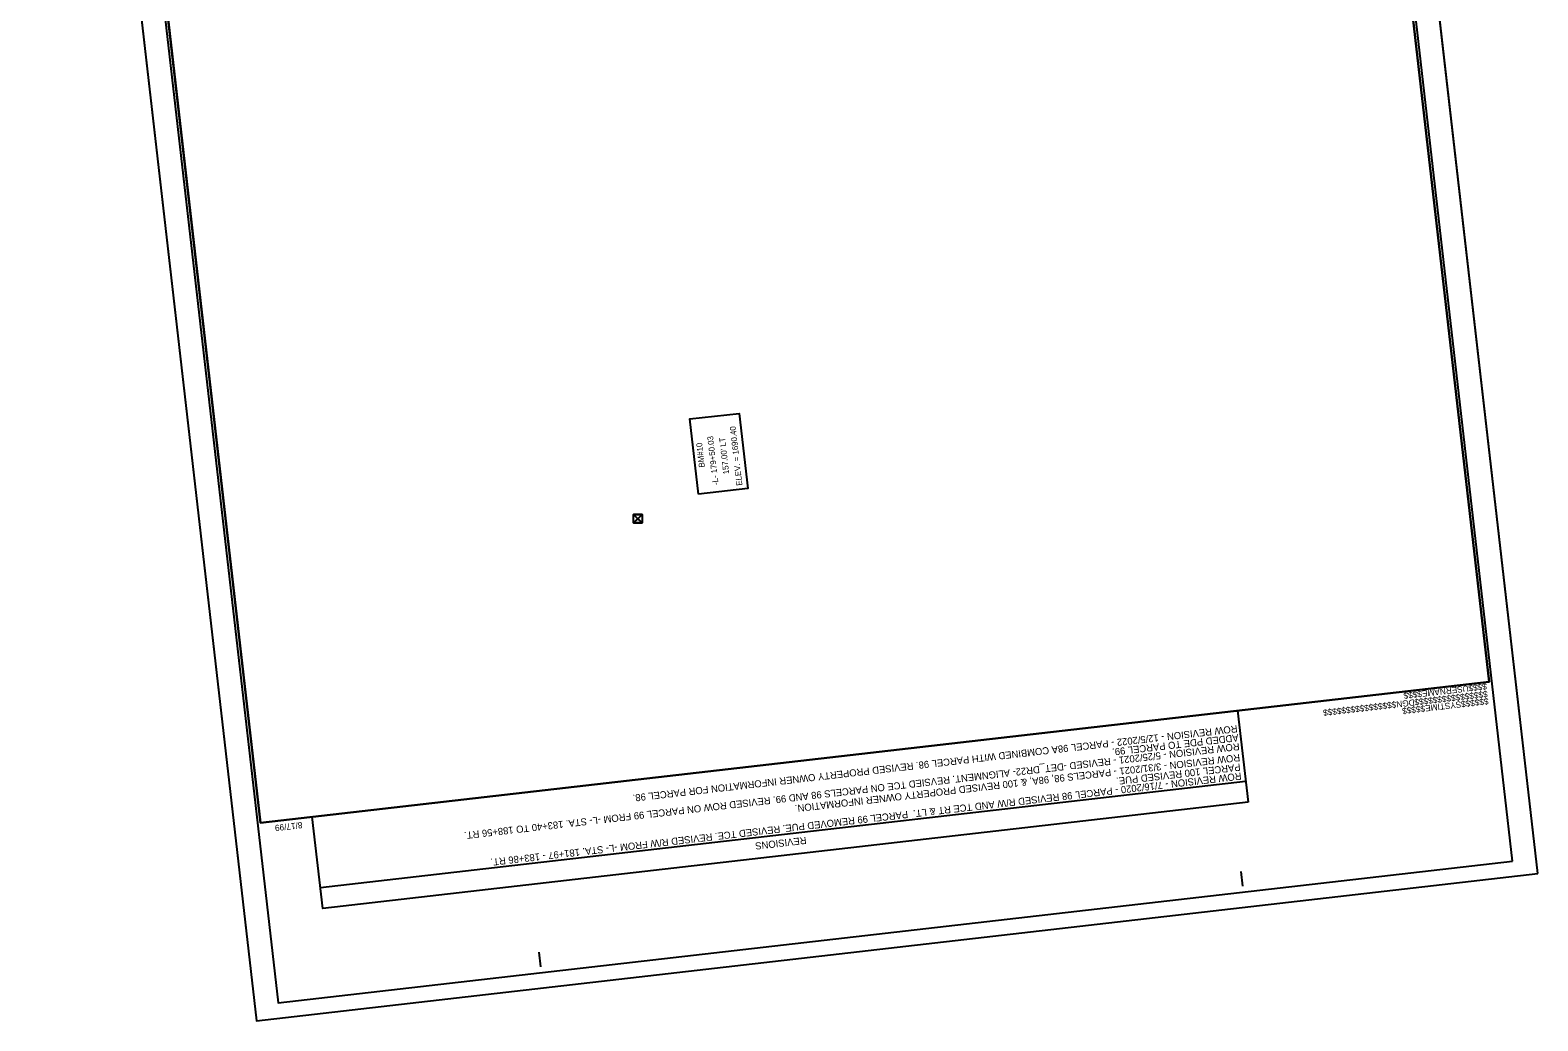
# Model space of a CAD drawing. Extents: x 474105 to 475385, y 502977 to 504774.
# Drawn here: x 474105 to 475385, y 502977 to 503817 of the extents above; entities that cross this region are included whole.
import ezdxf

# ---------------------------------------------------------------- set-up
doc = ezdxf.new("R2010")
doc.units = 0
for name, color, linetype in [('Default', 7, 'Continuous'), ('Prop Dimension Text', 7, 'Continuous'), ('Prop Grid Mask', 7, 'Continuous'), ('Sheet Block Revision CELL', 7, 'Continuous'), ('Sheet Cutting Line CELL', 7, 'Continuous'), ('Sheet Layout Plan Border', 7, 'Continuous'), ('Sheet Plan CELL', 7, 'Continuous'), ('Sheet Plan Layout CELL', 7, 'Continuous'), ('Sheet Plot Border Inside CELL', 7, 'Continuous'), ('Sheet Plot Border Outside CELL', 7, 'Continuous')]:
    doc.layers.add(name, color=color, linetype=linetype)

msp = doc.modelspace()

# ---------------------------------------------------------------- linework, layer by layer
at = {"layer": 'Default'}
msp.add_line((474621.3, 503402.8), (474621.3, 503402.8), dxfattribs=at)
msp.add_lwpolyline([(474617.7, 503406.4), (474624.9, 503406.4), (474624.9, 503399.2), (474617.7, 503399.2)], close=True, dxfattribs=at)
for points in [[(474624.9, 503406.4), (474617.7, 503399.2), (474621.3, 503402.8), (474624.9, 503399.2), (474617.7, 503406.4)], [(474621.3, 503402.8), (474624.9, 503406.4), (474617.7, 503406.4), (474621.3, 503402.8)], [(474621.3, 503402.8), (474617.7, 503399.2), (474624.9, 503399.2), (474621.3, 503402.8)]]:
    msp.add_lwpolyline(points, dxfattribs=at)
at = {"layer": 'Prop Grid Mask'}
msp.add_lwpolyline([(474672.7, 503423.5), (474665.4, 503487.4), (474707.3, 503492.2), (474714.6, 503428.3)], close=True, dxfattribs=at)
at = {"layer": 'Sheet Block Revision CELL'}
msp.add_line((475137.3, 503179.9), (474351.9, 503089.6), dxfattribs=at)
msp.add_lwpolyline([(475139.4, 503162.4), (474353.9, 503072.1), (474344.9, 503149.8), (475130.4, 503240)], close=True, dxfattribs=at)
at = {"layer": 'Sheet Cutting Line CELL'}
for p, q in [((475385.4, 503101.7), (475193.2, 504774.2)), ((474105.4, 504649.2), (474297.5, 502976.7)), ((474297.5, 502976.7), (475385.4, 503101.7))]:
    msp.add_line(p, q, dxfattribs=at)
at = {"layer": 'Sheet Layout Plan Border'}
msp.add_lwpolyline([(475344, 503264.5), (475192.3, 504585.3), (475112.8, 504576.2), (474903.6, 504485.2), (474306.1, 504619.7), (474302.1, 504654.7), (474324.9, 504456), (474152.5, 504436.2), (474168.8, 504438), (474279.8, 503999.6), (474242, 503987.6), (474254.8, 503913.6), (474216.7, 503877.5), (474300.9, 503144.7)], close=True, dxfattribs=at)
at = {"layer": 'Sheet Plan CELL'}
for p, q in [((475344, 503264.5), (475344, 503264.5)), ((474300.9, 503144.7), (474300.9, 503144.7)), ((475135, 503091.1), (475133.6, 503103.5)), ((474538.9, 503022.6), (474537.5, 503035))]:
    msp.add_line(p, q, dxfattribs=at)
for points in [[(474129.7, 504634.9), (474300.9, 503144.7), (475344, 503264.5), (475172.8, 504754.7)], [(475344, 503264.5), (474300.9, 503144.7), (474152.5, 504436.2), (474301.6, 504453.3), (474278.8, 504652), (475172.8, 504754.7)]]:
    msp.add_lwpolyline(points, close=True, dxfattribs=at)
at = {"layer": 'Sheet Plan Layout CELL'}
msp.add_lwpolyline([(474300.9, 503144.7), (475344, 503264.5), (475172.8, 504754.7), (474339.8, 504659), (474367.1, 504421.3), (474157, 504397.2)], close=True, dxfattribs=at)
at = {"layer": 'Sheet Plot Border Inside CELL'}
msp.add_lwpolyline([(475364, 503112.3), (475173.9, 504767.4), (474125.8, 504647), (474315.9, 502991.9)], close=True, dxfattribs=at)
at = {"layer": 'Sheet Plot Border Outside CELL'}
msp.add_lwpolyline([(475385.4, 503101.7), (475193.2, 504774.2), (474105.4, 504649.2), (474297.5, 502976.7)], close=True, dxfattribs=at)

# ---------------------------------------------------------------- texts
at = {"layer": 'Prop Dimension Text'}
for s, p in [('-L- 179+50.03', (474689.9, 503431.6)), ('ELEV. = 1690.40', (474710.1, 503431.1)), ('BM#10', (474678.2, 503446.5)), ("157.00' LT", (474698.9, 503440.8))]:
    msp.add_text(s, height=5, rotation=96.5773, dxfattribs=at).set_placement(p)
at = {"layer": 'Sheet Block Revision CELL'}
for s, p in [('ROW REVISION - 12/5/2022 - PARCEL 98A COMBINED WITH PARCEL 98. REVISED PROPERTY OWNER INFORMATION FOR PARCEL 98.', (475130, 503227.6)), ('ADDED PDE TO PARCEL 99. ', (475130.9, 503220)), ('ROW REVISION - 5/25/2021 - REVISED -DET_DR22- ALIGNMENT. REVSIED TCE ON PARCELS 98 AND 99. REVISED ROW ON PARCEL 99 FROM -L- STA. 183+40 TO 188+56 RT. ', (475131.8, 503212.5)), ('ROW REVISION - 3/31/2021 - PARCELS 98, 98A, & 100 REVISED PROPERTY OWNER INFORMATION. ', (475132.2, 503203.1)), ('PARCEL 100 REVISED PUE.', (475132.6, 503195)), ('ROW REVISION - 7/16/2020 - PARCEL 98 REVISED R/W AND TCE RT & LT.  PARCEL 99 REMOVED PUE. REVISED TCE. REVISED R/W FROM -L- STA. 181+97 - 183+86 RT.', (475133.4, 503187.4)), ('REVISIONS', (474764.1, 503132.9))]:
    msp.add_text(s, height=6, rotation=186.5538, dxfattribs=at).set_placement(p)
at = {"layer": 'Sheet Plan CELL'}
for s, p in [('$$$$$$$$$$$$$$$$DGN$$$$$$$$$$$$$$$$', (475342.5, 503256.7)), ('$$$$USERNAME$$$$', (475341.8, 503263.2)), ('$$$$$$SYSTIME$$$$$', (475343.3, 503250.6)), ('8/17/99', (474336.2, 503145.5))]:
    msp.add_text(s, height=5.25, rotation=186.5538, dxfattribs=at).set_placement(p)

doc.saveas('drawing.dxf')
